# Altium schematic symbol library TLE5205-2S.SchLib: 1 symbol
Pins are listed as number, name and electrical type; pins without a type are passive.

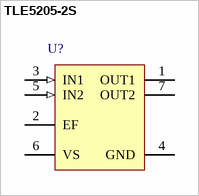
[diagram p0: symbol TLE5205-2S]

## TLE5205-2S
designator U?
5 A H-Bridge for DC-Motor Applications, 6 to 40 V, 220 mOhm RDS(on), PG-TO220-7-12, Tube, Green; Manufacturer: Infineon; PartNumber: TLE5205-2S; Current Limit (min.): 6 A; Green: TRUE; Operating Range: 6 to 40 V; Quiescent Current (max.): 10 mA; RthJC (max): 3 K/W
footprint INF-PG-TO220-7-12 (FM, 7-Leads, Body 10x4.4mm, Pitch 1.27mm)
pins: 1 OUT1 (power) "Output of Channel 1; Short-circuit protected; integrated freewheeling diodes for inductive loads.", 2 EF (oc) "Error Flag; TTL/CMOS compatible output for error detection; (open drain)", 3 IN1 (in) "Control Input 1; TTL/CMOS compatible", 4 GND (power) "Ground; internally connected to tab", 5 IN2 (in) "Control Input 2; TTL/CMOS compatible", 6 VS (power) "Supply Voltage; block to GND", 7 OUT2 (power) "Output of Channel 2; Short-circuit protected; integrated freewheeling diodes for inductive loads."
